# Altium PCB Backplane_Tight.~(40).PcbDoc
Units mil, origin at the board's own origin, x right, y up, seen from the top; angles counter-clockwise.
Board outline 6940 x 1650 mil, 6 copper layers (Top Layer, AGND, +5V, DGND, VCC, Bottom Layer), stack 50.76 mil thick; 21 components, 91 nets, 243 pads, 0 vias.
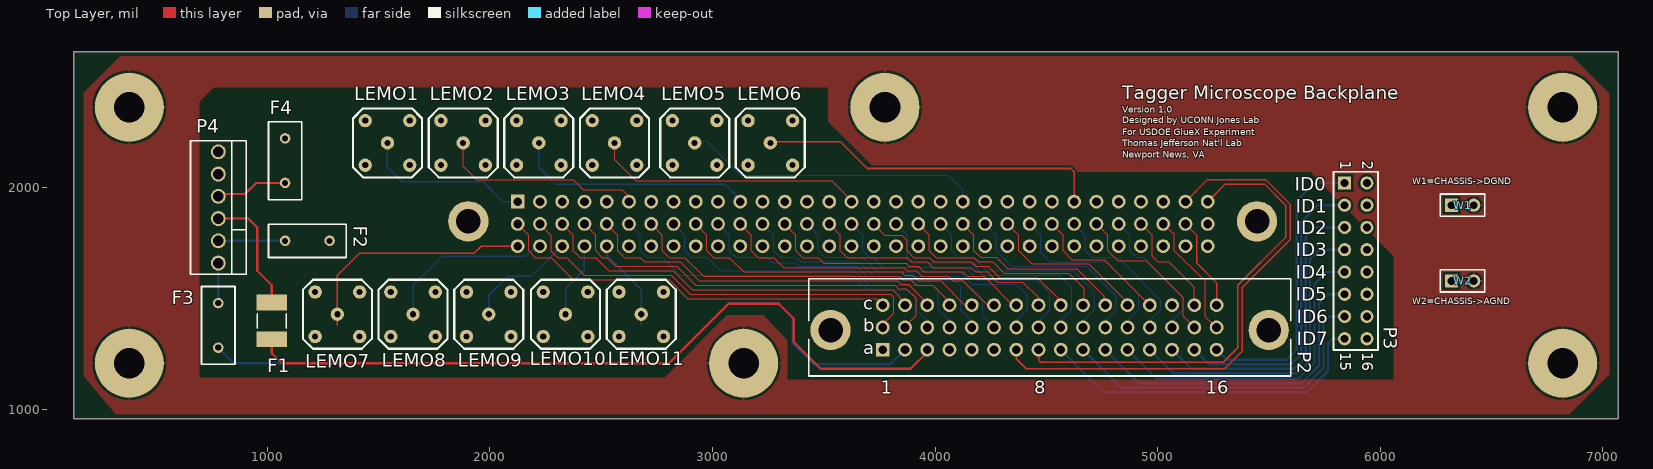
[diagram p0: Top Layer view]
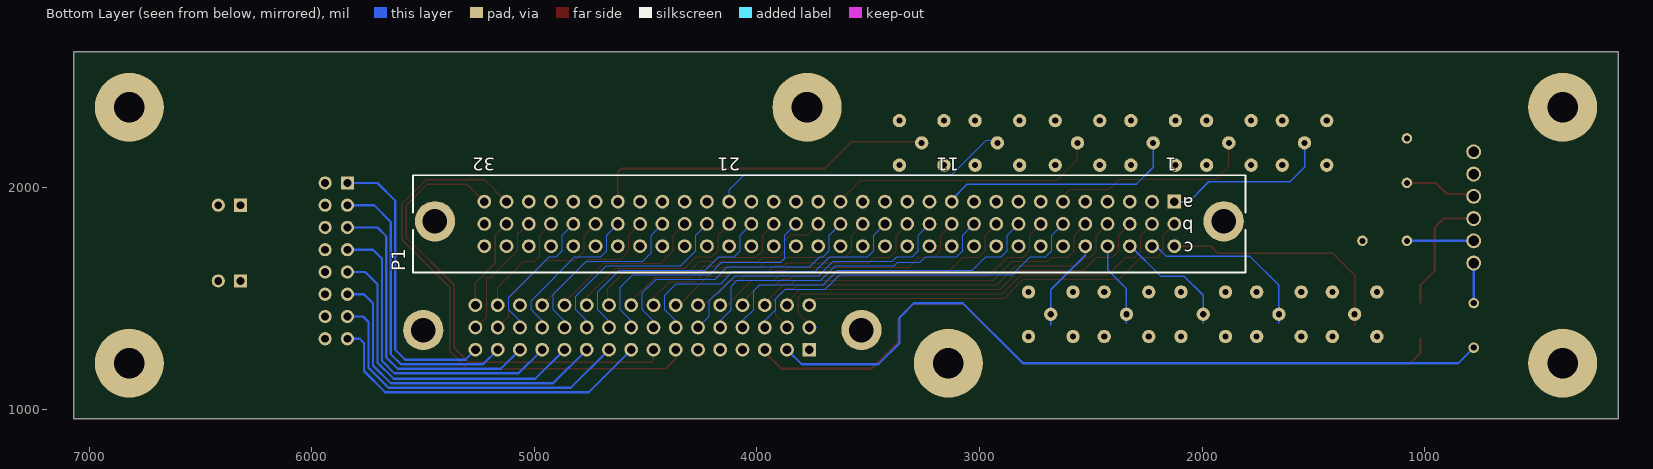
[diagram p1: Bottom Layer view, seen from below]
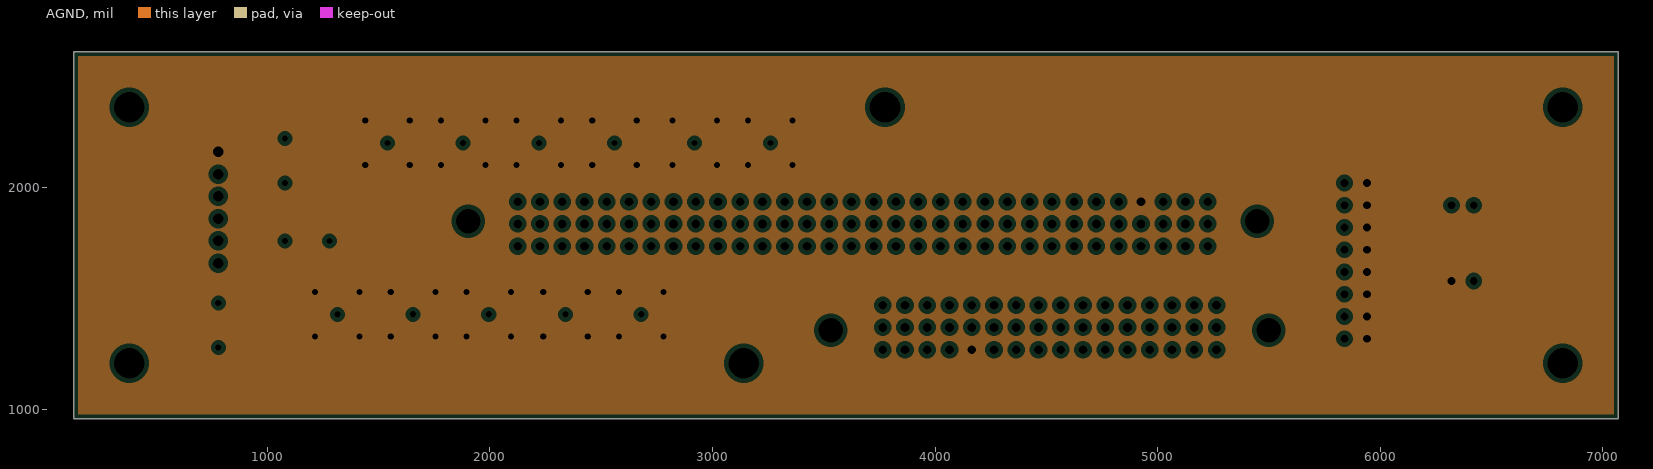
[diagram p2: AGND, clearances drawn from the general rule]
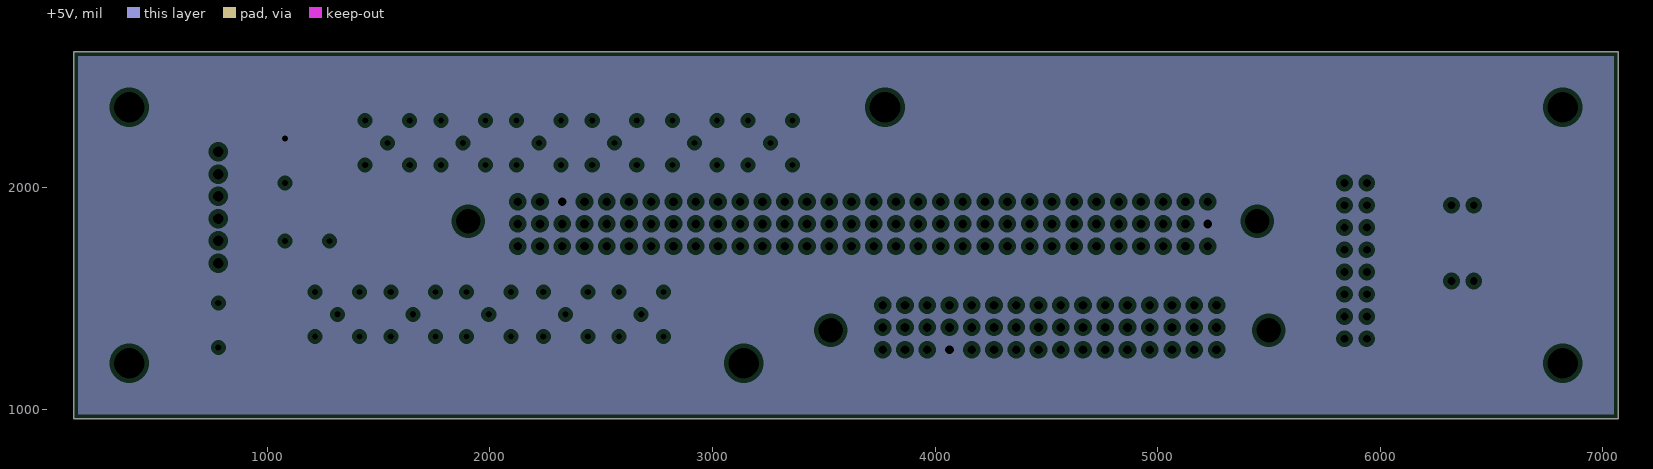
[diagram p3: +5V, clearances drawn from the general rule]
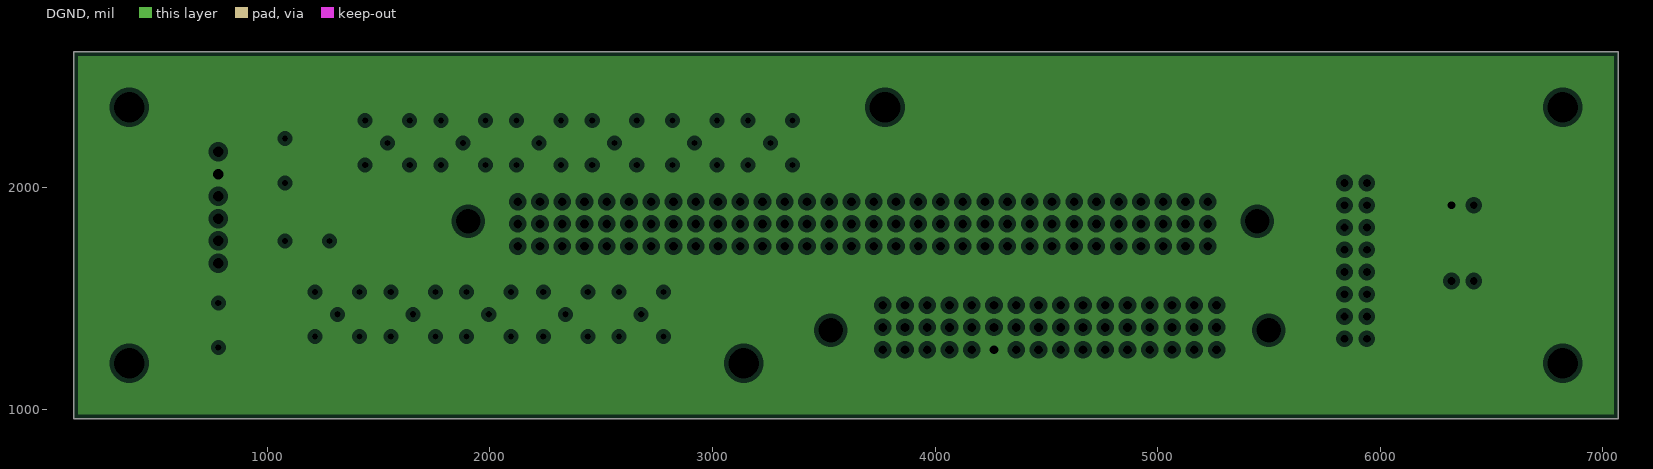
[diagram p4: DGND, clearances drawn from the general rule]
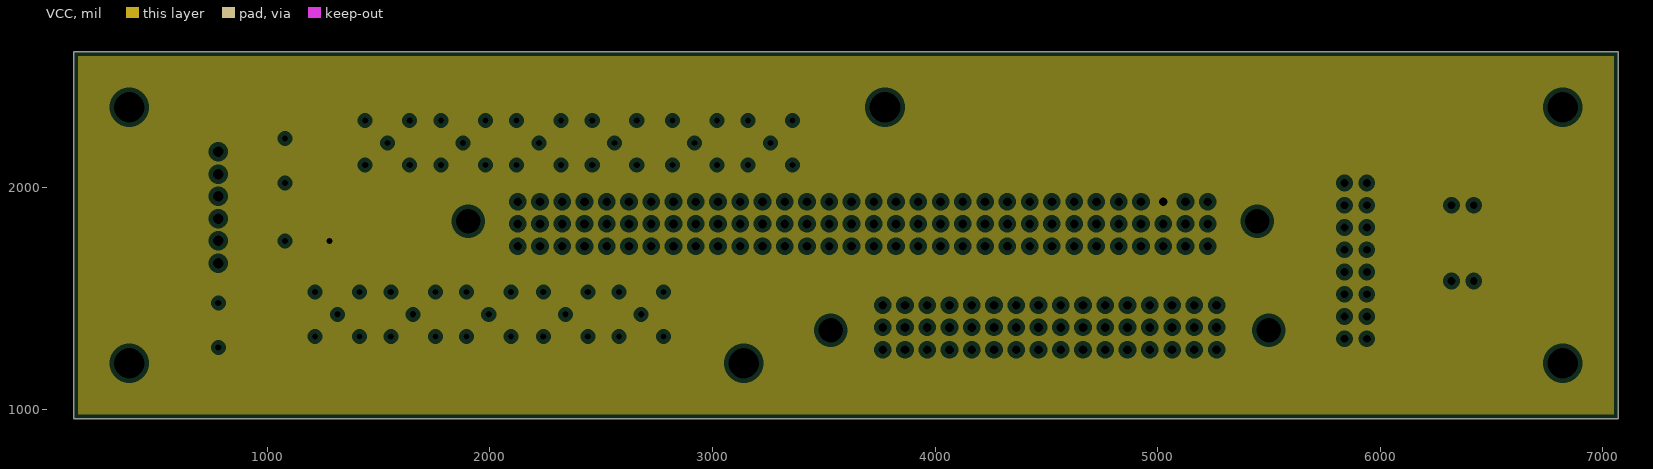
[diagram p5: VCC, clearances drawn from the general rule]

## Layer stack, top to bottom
Top Layer: signal copper 1.4
Dielectric: prepreg 5.1, FR-4, Dk 4.8
AGND: plane copper 1.4, net AGND
Dielectric: core 10.72, FR-4, Dk 4.8
+5V: plane copper 1.4, net +5V
Dielectric: prepreg 10.72, FR-4, Dk 4.8
DGND: plane copper 1.4, net DGND
Dielectric: core 10.72, FR-4, Dk 4.8
VCC: plane copper 1.4, net VCC
Dielectric: prepreg 5.1, FR-4, Dk 4.8
Bottom Layer: signal copper 1.4

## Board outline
130,960 7070,960 7070,2610 130,2610

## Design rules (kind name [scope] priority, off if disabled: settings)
Clearance Clearance_BIAS [InNetClass('BIAS')] p1: gap=15
Clearance [All] p2: gap=10
ComponentClearance [All] p1: gap=10 collisioncheckmode=3 verticalgap=10
PlaneClearance [All] p1: clearance=20
PlaneConnect [All] p1: planeconnectstyle=Relief reliefexpansion=20 reliefentries=4 reliefconductorwidth=10 reliefairgap=10
PolygonConnect [All] p1: connectstyle=Relief reliefconductorwidth=10 reliefentries=4 polygonreliefangle="90 Angle"
RoomDefinition LEMO [InComponentClass('LEMO')] p1: confinementstyle=ConfineIn formatcopy=TRUE lockcomponents=FALSE outline 275,1060 6580,1060 6580,2460 275,2460
RoomDefinition "Digital Connector" [InComponentClass('Digital Connector')] p2: confinementstyle=ConfineIn formatcopy=TRUE lockcomponents=FALSE outline 3170,1046 6595,1046 6595,2200 3170,2200
RoomDefinition "Analog Connector" [InComponentClass('Analog Connector')] p3: confinementstyle=ConfineIn formatcopy=TRUE lockcomponents=FALSE outline 1595,1516 5615,1516 5615,2191 1595,2191
RoutingVias [All] p1: holewidth=28 width=50 viastyle="Through Hole" minholewidth=28 minwidth=50 maxholewidth=28 maxwidth=50
SolderMaskExpansion [All] p1: expansion=4
SupplyNets VCC [OnLayer('VCC')] p1: voltage=10.00
SupplyNets +5V [OnLayer('+5V')] p2: voltage=5.000
SupplyNets DGND [OnLayer(DGND)] p3: voltage=0.000
SupplyNets AGND [OnLayer('AGND')] p4: voltage=0.000
TestPointUsage [All] p1: valid=0 allowmultiple=FALSE
Testpoint [All] p1: side=15 testpointundercomponent=TRUE minsize=40 maxsize=100 preferedsize=60 minholesize=0 maxholesize=40 preferedholesize=32 testpointgrid=1 style=1023 order=0123456789
Width Width_CHASSISGND [InNet('CHASSISGND')] p1: maxlimit=100 minlimit=10 preferedwidth=10
Width [All] p2: maxlimit=10 minlimit=5 preferedwidth=7
Width Width_BIAS [InNetClass('BIAS')] p3: maxlimit=10 minlimit=4 preferedwidth=5
Width Width_SIPMOUT [InNetClass('SIPMOUT')] p4: maxlimit=7.35 minlimit=2.1 preferedwidth=7.35 impedancedriven=TRUE minimp=50.000000 maximp=80.000000 favimp=50.000000
16 further rules are at their usual default settings.

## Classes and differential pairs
component class LEMO: F1 F2 F3 F4 LEMO1 LEMO2 LEMO3 LEMO4 LEMO5 LEMO6 LEMO7 LEMO8 LEMO9 LEMO10 LEMO11 P4 W1 W2
component class "Digital Connector": P2 P3 R?
component class "Analog Connector": P1
net class SIPMOUT: SIPMOUT1 SIPMOUT2 SIPMOUT3 SIPMOUT4 SIPMOUT5 SIPMOUT6 SIPMOUT7 SIPMOUT8 SIPMOUT9 SIPMOUT10 SIPMOUT11 SIPMOUT12 SIPMOUT13 SIPMOUT14 SIPMOUT15 SIPMOUT16 SIPMOUT17 SIPMOUT18 SIPMOUT19 SIPMOUT20 SIPMOUT21 SIPMOUT22 SIPMOUT23 SIPMOUT24 SIPMOUT25 SIPMOUT26 SIPMOUT27 SIPMOUT28 SIPMOUT29 SIPMOUT30 SIPMOUT31 SIPMOUT32 SUMMED1 SUMMED2 SUMMED3 SUMMED4 SUMMED5 SUMMED6
net class BIAS: SIPMBIAS1 SIPMBIAS2 SIPMBIAS3 SIPMBIAS4 SIPMBIAS5 SIPMBIAS6 SIPMBIAS7 SIPMBIAS8 SIPMBIAS9 SIPMBIAS10 SIPMBIAS11 SIPMBIAS12 SIPMBIAS13 SIPMBIAS14 SIPMBIAS15 SIPMBIAS16 SIPMBIAS17 SIPMBIAS18 SIPMBIAS19 SIPMBIAS20 SIPMBIAS21 SIPMBIAS22 SIPMBIAS23 SIPMBIAS24 SIPMBIAS25 SIPMBIAS26 SIPMBIAS27 SIPMBIAS28 SIPMBIAS29 SIPMBIAS30 SIPMBIAS31 SIPMBIAS32

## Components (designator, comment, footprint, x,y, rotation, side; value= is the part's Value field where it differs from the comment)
F1 "Fuse Thermal" CAPC4532M 1020,1400 r270 top
F2 "Fuse Thermal" RAD-0.2 1180,1760 r0 top
F3 "Fuse Thermal" RAD-0.2 780,1380 r270 top
F4 "Fuse Thermal" RAD-0.2 1080,2120 r90 top
LEMO1 "LEMO EPA.00" "LEMO EPA.00" 1540,2200 r0 top
LEMO2 "LEMO EPA.00" "LEMO EPA.00" 1880,2200 r0 top
LEMO3 "LEMO EPA.00" "LEMO EPA.00" 2220,2200 r0 top
LEMO4 "LEMO EPA.00" "LEMO EPA.00" 2560,2200 r0 top
LEMO5 "LEMO EPA.00" "LEMO EPA.00" 2920,2200 r0 top
LEMO6 "LEMO EPA.00" "LEMO EPA.00" 3260,2200 r0 top
LEMO7 "LEMO EPA.00" "LEMO EPA.00" 1315,1430 r0 top
LEMO8 "LEMO EPA.00" "LEMO EPA.00" 1655,1430 r0 top
LEMO9 "LEMO EPA.00" "LEMO EPA.00" 1995,1430 r0 top
LEMO10 "LEMO EPA.00" "LEMO EPA.00" 2340,1430 r0 top
LEMO11 "LEMO EPA.00" "LEMO EPA.00" 2680,1430 r0 top
P1 "DIN41612 96 pin, Backplane" EURO2.54-2V96 3675,1836 r0 bottom
P2 "DIN41612 48 pin, Backplane" EURO2.54-2V48 4515,1371 r0 top
P3 "Header 8X2" HDR2X8 5840,2020 r270 top
P4 "Header 6" KK6373 780,2160 r270 top
W1 "Jumper" HDR1X2 6320,1920 r0 top
W2 "Jumper" HDR1X2 6320,1580 r0 top

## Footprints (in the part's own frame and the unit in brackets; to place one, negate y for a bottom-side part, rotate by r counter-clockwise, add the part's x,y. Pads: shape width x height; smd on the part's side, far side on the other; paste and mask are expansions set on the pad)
CAPC4532M [mm] "Chip Capacitor, Body 4.5x3.2mm, IPC Low Density"
  rect 1.8x3.5 smd: 1(-2.1,0) 2(2.1,0)
  silkscreen extent -0.8,-1.65 0.8,1.65, body extent -2.4,-1.7 2.4,1.7, height 1.35
EURO2.54-2V48 [mil] "Connector; DIN 41612, Type 2C, Thru-Hole; Rows a+b+c, 48 Position; Vertical"
  round 181.1 hole 110.24: 17(-984.25,-11.81) 18(984.25,-11.81)
  rect 62x62 hole 39.37: A1(-750,-100)
  round 62 hole 39.37: A2(-650,-100) A3(-550,-100) A4(-450,-100) A5(-350,-100) A6(-250,-100) A7(-150,-100) A8(-50,-100) A9(50,-100) A10(150,-100) A11(250,-100) A12(350,-100) A13(450,-100) A14(550,-100) A15(650,-100) A16(750,-100) B1(-750,0) B2(-650,0) B3(-550,0) B4(-450,0) B5(-350,0) B6(-250,0) B7(-150,0) B8(-50,0) B9(50,0) B10(150,0) B11(250,0) B12(350,0) B13(450,0) B14(550,0) B15(650,0) B16(750,0) C1(-750,100) C2(-650,100) C3(-550,100) C4(-450,100) C5(-350,100) C6(-250,100) C7(-150,100) C8(-50,100) C9(50,100) C10(150,100) C11(250,100) C12(350,100) C13(450,100) C14(550,100) C15(650,100) C16(750,100)
  silkscreen extent -1083,-219 1083,219
EURO2.54-2V96 [mil] "Connector; DIN 41612, Type C, Thru-Hole; Rows a+b+c, 96 Position; Vertical"
  round 181.1 hole 110.24: 33(-1771.65,-11.81) 34(1771.65,-11.81)
  rect 62x62 hole 39.37: A1(-1550,-100)
  round 62 hole 39.37: A2(-1450,-100) A3(-1350,-100) A4(-1250,-100) A5(-1150,-100) A6(-1050,-100) A7(-950,-100) A8(-850,-100) A9(-750,-100) A10(-650,-100) A11(-550,-100) A12(-450,-100) A13(-350,-100) A14(-250,-100) A15(-150,-100) A16(-50,-100) A17(50,-100) A18(150,-100) A19(250,-100) A20(350,-100) A21(450,-100) A22(550,-100) A23(650,-100) A24(750,-100) A25(850,-100) A26(950,-100) A27(1050,-100) A28(1150,-100) A29(1250,-100) A30(1350,-100) A31(1450,-100) A32(1550,-100) B1(-1550,0) B2(-1450,0) B3(-1350,0) B4(-1250,0) B5(-1150,0) B6(-1050,0) B7(-950,0) B8(-850,0) B9(-750,0) B10(-650,0) B11(-550,0) B12(-450,0) B13(-350,0) B14(-250,0) B15(-150,0) B16(-50,0) B17(50,0) B18(150,0) B19(250,0) B20(350,0) B21(450,0) B22(550,0) B23(650,0) B24(750,0) B25(850,0) B26(950,0) B27(1050,0) B28(1150,0) B29(1250,0) B30(1350,0) B31(1450,0) B32(1550,0) C1(-1550,100) C2(-1450,100) C3(-1350,100) C4(-1250,100) C5(-1150,100) C6(-1050,100) C7(-950,100) C8(-850,100) C9(-750,100) C10(-650,100) C11(-550,100) C12(-450,100) C13(-350,100) C14(-250,100) C15(-150,100) C16(-50,100) C17(50,100) C18(150,100) C19(250,100) C20(350,100) C21(450,100) C22(550,100) C23(650,100) C24(750,100) C25(850,100) C26(950,100) C27(1050,100) C28(1150,100) C29(1250,100) C30(1350,100) C31(1450,100) C32(1550,100)
  silkscreen extent -1870,-219 1870,219
HDR1X2 [mm] "Connector; Header; 2 Position"
  rect 1.5x1.5 hole 0.9: 1(0,0)
  round 1.5 hole 0.9: 2(2.54,0)
  silkscreen extent -1.27,-1.27 3.81,1.27
HDR2X8 [mm] "Connector; Header; 8x2 Position"
  rect 1.5x1.5 hole 0.9: 1(0,0)
  round 1.5 hole 0.9: 2(0,2.54) 3(2.54,0) 4(2.54,2.54) 5(5.08,0) 6(5.08,2.54) 7(7.62,0) 8(7.62,2.54) 9(10.16,0) 10(10.16,2.54) 11(12.7,0) 12(12.7,2.54) 13(15.24,0) 14(15.24,2.54) 15(17.78,0) 16(17.78,2.54)
  silkscreen extent -1.27,-1.27 19.05,3.81
KK6373 [mil]
  round 67 hole 47.24: 1(0,0) 2(100,0) 3(200,0) 4(300,0) 5(400,0) 6(500,0)
  silkscreen extent -50,-125 550,125
"LEMO EPA.00" [mil]
  round 60 hole 27.56: 0(0,0) 1(-100,100) 2(100,100) 3(100,-100) 4(-100,-100)
  silkscreen extent -155,-155 155,155
RAD-0.2 [mm] "Jumper Wire; 2 Leads"
  round 1.2 hole 0.7: 1(-2.54,0) 2(2.54,0)
  silkscreen extent -4.44,-1.91 4.44,1.91

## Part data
F1 F2 F3 F4: "Thermal Fuse"
P3: library part "Header 5X2", "Header, 5-Pin, Dual row"
P4: "Header, 6-Pin"
W1 W2: "Jumper Wire"

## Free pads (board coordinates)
  round 310 hole 138 unplated: 0(380,1210) 0(380,2360) 0(3140,1210) 0(3775,2360) 0(6820,1210) 0(6820,2360)

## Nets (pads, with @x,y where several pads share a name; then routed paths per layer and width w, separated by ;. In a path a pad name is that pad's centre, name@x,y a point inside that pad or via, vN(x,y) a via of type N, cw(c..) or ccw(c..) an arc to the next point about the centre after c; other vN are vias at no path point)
+5V: F4.2 P1.A3 P1.B32 P2.A4
+5V_FUSE: F4.1 P4.3 | length 325.7
  Top Layer w10: P4.3@775,1970 900,1970 950,2020 F4.1
+210V: F3.2 P2.A2 | length 3434.4
  Bottom Layer w10: F3.2 850,1210 2805,1210 3075,1480 3295,1480 3360,1415 3360,1300 3455,1205 3799,1205 P2.A2
+210V_FUSE: F3.1 P4.6 | length 180
  Bottom Layer w10: F3.1 P4.6
-5V: F1.2 P2.A3 | length 3361.5
  Top Layer w10: F1.2 1020,1255 1065,1210 2805,1210 3072.5,1477.5 3297.5,1477.5 3365,1410 3365,1305 3485,1185 3890,1185 3965,1260 P2.A3
-5V_FUSE: F1.1 P4.4 | length 565.8
  Top Layer w10: P4.4@770,1860 915,1860 955,1820 955,1625 1020,1560 F1.1
ADC_EXT1: P1.A31 P2.A7 | length 2413.4
  Top Layer w7: P2.A7 4365,1230 4410,1185 5300,1185 5380,1265 5380,1550 5595,1765 5595,1925 5485,2035 5224,2035 P1.A31
ADC_EXT2: P1.A32 P2.A8 | length 2123.2
  Top Layer w7: P2.A8 4465,1225 4475,1215 5295,1215 5360,1280 5360,1560 5575,1775 5575,1920 5480,2015 5304,2015 P1.A32
AGND: LEMO1.1 LEMO1.2 LEMO1.3 LEMO1.4 LEMO2.1 LEMO2.2 LEMO2.3 LEMO2.4 LEMO3.1 LEMO3.2 LEMO3.3 LEMO3.4 LEMO4.1 LEMO4.2 LEMO4.3 LEMO4.4 LEMO5.1 LEMO5.2 LEMO5.3 LEMO5.4 LEMO6.1 LEMO6.2 LEMO6.3 LEMO6.4 LEMO7.1 LEMO7.2 LEMO7.3 LEMO7.4 LEMO8.1 LEMO8.2 LEMO8.3 LEMO8.4 LEMO9.1 LEMO9.2 LEMO9.3 LEMO9.4 LEMO10.1 LEMO10.2 LEMO10.3 LEMO10.4 LEMO11.1 LEMO11.2 LEMO11.3 LEMO11.4 P1.A29 P2.A5 P3.2 P3.4 P3.6 P3.8 P3.10 P3.12 P3.14 P3.16 P4.1 W2.1
CHASSISGND: pad.0 W1.2 W2.2
CP2201/LA: P2.A1
DGND: P2.A6 P4.2 W1.1
ID0: P2.A16 P3.1 | length 1314.4
  Bottom Layer w10: P2.A16 5310,1226 5580,1226 5625,1271 5625,1940 5705,2020 P3.1
ID1: P2.A15 P3.3 | length 1346.5
  Bottom Layer w10: P2.A15 5231,1205 5599,1205 5645,1251 5645,1845 5720,1920 P3.3
ID2: P2.A14 P3.5 | length 1392.3
  Bottom Layer w10: P2.A14 5151,1185 5614,1185 5665,1236 5665,1780 5705,1820 P3.5
ID3: P2.A13 P3.7 | length 1417.7
  Bottom Layer w10: P2.A13 5071,1165 5629,1165 5685,1221 5685,1680 5725,1720 P3.7
ID4: P2.A12 P3.9 | length 1434.4
  Bottom Layer w10: P2.A12 4996,1140 5632.28,1140 5705,1212.72 5705,1565 5760,1620 P3.9
ID5: P2.A11 P3.11 | length 1467.3
  Bottom Layer w10: P2.A11 4916,1120 5645,1120 5725,1200 5725,1480 5765,1520 P3.11
ID6: P2.A10 P3.13 | length 1498.5
  Bottom Layer w10: P2.A10 4836,1100 5655,1100 5745,1190 5745,1395 5770,1420 P3.13
ID7: P2.A9 P3.15 | length 1526.7
  Bottom Layer w10: P2.A9 4756,1080 5670,1080 5765,1175 5765,1300 5785,1320 P3.15
SIPMBIAS1: P1.B1 P2.C1 | length 1832.8
  Top Layer w5: P1.B1 2175,1786 2175,1715 2205,1685 2275,1685 2375,1585 2805,1585 2890,1500 3736,1500 P2.C1
SIPMBIAS2: P1.B2 P2.B1 | length 1974.4
  Top Layer w5: P1.B2 2225,1835 2276.5,1783.5 2276.5,1713.5 2305,1685 2345,1685 2425,1605 2815,1605 2900,1520 3800,1520 3815,1505 3815,1435 3765,1385 P2.B1
  Bottom Layer w5: P1.B2@2225,1825 P1.B2 ; P2.B1@3765,1376 P2.B1 P2.B1@3770,1371
  Bottom Layer w10: P2.B1@3735,1371 P2.B1
SIPMBIAS3: P1.B3 P2.C2 | length 1741
  Top Layer w5: P1.B3 2375,1786 2375,1715 2405,1685 2475,1685 2535,1625 2825,1625 2910,1540 3810,1540 3865,1485 P2.C2
SIPMBIAS4: P1.B4 P2.B2 | length 1851.5
  Top Layer w5: P1.B4 2475,1786 2475,1715 2505,1685 2525,1685 2565,1645 2840,1645 2925,1560 3820,1560 3835,1545 3871.72,1545 3915,1501.72 3915,1425 3865,1375 P2.B2
  Bottom Layer w5: P2.B2 P2.B2@3865,1401
SIPMBIAS5: P1.B5 P2.C3 | length 1663.1
  Top Layer w5: P1.B5 2575,1786 2575,1715 2605,1685 2675,1685 2695,1665 2855,1665 2940,1580 3830,1580 3845,1565 3880,1565 3965,1480 P2.C3
  Bottom Layer w5: P2.C3 P2.C3@3965,1496
SIPMBIAS6: P1.B6 P2.B3 | length 1634.6
  Bottom Layer w5: P1.B6 2675,1786 2675,1716 2705,1686 2775,1686 2855,1606 3630,1606 3695,1541 3875,1541 3920,1496 3920,1491 3915,1486 3915,1451 3965,1401 P2.B3 P2.B3@3975,1371
SIPMBIAS7: P1.B7 P2.C4 | length 1546.1
  Top Layer w5: P1.B7 2775,1786 2775,1715 2805,1685 2875,1685 2960,1600 3840,1600 3855,1585 3890,1585 3915,1560 3990,1560 4075,1475 P2.C4@4080,1475
SIPMBIAS8: P1.B8 P2.B4 | length 1541
  Bottom Layer w5: P1.B8 2875,1786 2875,1716 2905,1686 2975,1686 3035,1626 3640,1626 3705,1561 3990,1561 4015,1536 4015,1451 4065,1401 P2.B4
SIPMBIAS9: P1.B9 P2.C5 | length 1432.8
  Top Layer w5: P1.B9 2975,1786 2975,1715 3005,1685 3075,1685 3140,1620 3850,1620 3865,1605 3900,1605 3925,1580 4025,1580 4134,1471 P2.C5
SIPMBIAS10: P1.B10 P2.B5 | length 1452.7
  Bottom Layer w5: P1.B10 3075,1786 3075,1716 3105,1686 3245,1686 3270,1661 3370,1661 3385,1646 3651.41,1646 3716.41,1581 4090,1581 4115,1556 4115,1451 4165,1401 P2.B5
SIPMBIAS11: P1.B11 P2.C6 | length 1332.8
  Top Layer w5: P1.B11 3175,1786 3175,1715 3205,1685 3275,1685 3320,1640 3860,1640 3875,1625 3915,1625 3940,1600 4060,1600 4080,1580 4127,1580 4236,1471 P2.C6
SIPMBIAS12: P1.B12 P2.B6 | length 1334.6
  Bottom Layer w5: P1.B12 3275,1786 3275,1716 3305,1686 3375,1686 3395,1666 3660,1666 3725,1601 4100,1601 4180,1521 4185,1521 4215,1491 4215,1421 P2.B6 P2.B6@4265,1391
SIPMBIAS13: P1.B13 P2.C7 | length 1232.8
  Top Layer w5: P1.B13 3375,1786 3375,1715 3405,1685 3475,1685 3500,1660 3870,1660 3885,1645 3925,1645 3950,1620 4125,1620 4145,1600 4220,1600 4349,1471 P2.C7
SIPMBIAS14: P1.B14 P2.B7 | length 1334.3
  Bottom Layer w5: P1.B14 3475,1786 3475,1716 3505,1686 3675,1686 3740,1621 4110,1621 4165,1566 4365,1566 4415,1516 4415,1451 4365,1401 P2.B7 P2.B7@4370,1371
SIPMBIAS15: P1.B15 P2.C8 | length 1152.7
  Top Layer w5: P1.B15 3575,1786 3575,1715 3605,1685 3875,1685 3895,1665 3965,1665 3990,1640 4160,1640 4180,1620 4235,1620 4280,1575 4395,1575 4465,1505 P2.C8
SIPMBIAS16: P1.B16 P2.B8 | length 1240.1
  Bottom Layer w5: P1.B16 3675,1786 3675,1716 3705,1686 3720,1686 3765,1641 4135,1641 4190,1586 4455,1586 4515,1526 4515,1451 4465,1401 P2.B8 P2.B8@4470,1371
SIPMBIAS17: P1.B17 P2.C9 | length 1029.3
  Top Layer w5: P1.B17 3725,1835 3775,1785 3850,1785 3875,1760 3875,1715 3905,1685 3975,1685 3995,1665 4165,1665 4185,1645 4240,1645 4290,1595 4460,1595 4565,1490 P2.C9
SIPMBIAS18: P1.B18 P2.B9 | length 1170.3
  Bottom Layer w5: P1.B18 3875,1786 3875,1681 3895,1661 4160,1661 4215,1606 4560,1606 4615,1551 4615,1451 4565,1401 P2.B9
SIPMBIAS19: P1.B19 P2.C10 | length 996.5
  Top Layer w5: P1.B19 3975,1786 3975,1715 4005,1685 4175,1685 4195,1665 4260,1665 4310,1615 4600,1615 4670,1545 4670,1471 4669,1470 P2.C10@4655,1470
SIPMBIAS20: P1.B20 P2.B10 | length 1048.1
  Bottom Layer w5: P1.B20 4075,1786 4075,1716 4105,1686 4175,1686 4235,1626 4620,1626 4715,1531 4715,1451 4665,1401 P2.B10 P2.B10@4675,1371
SIPMBIAS21: P1.B21 P2.C11 | length 870.6
  Top Layer w5: P1.B21 4175,1786 4175,1716 4205,1686 4275,1686 4326,1635 4636,1635 4760,1511 P2.C11@4760,1461 ; P2.C11 P2.C11@4765,1481
SIPMBIAS22: P1.B22 P2.B11 | length 926.3
  Bottom Layer w5: P1.B22 4275,1786 4275,1716 4345,1646 4680,1646 4815,1511 4815,1451 4765,1401 P2.B11
SIPMBIAS23: P1.B23 P2.C12 | length 738.1
  Top Layer w5: P1.B23 4375,1786 4375,1716 4435,1656 4690,1656 4865,1481 P2.C12
SIPMBIAS24: P1.B24 P2.B12 | length 838.1
  Bottom Layer w5: P1.B24 4475,1786 4475,1706 4515,1666 4770,1666 4915,1521 4915,1451 4865,1401 P2.B12
SIPMBIAS25: P1.B25 P2.C13 | length 639.3
  Top Layer w5: P1.B25@4520,1841 4575,1786 4575,1716 4615,1676 4760,1676 P2.C13
SIPMBIAS26: P1.B26 P2.B13 | length 724.6
  Bottom Layer w5: P1.B26 4675,1786 4675,1716 4705,1686 4820,1686 5015,1491 5015,1451 4965,1401 P2.B13 P2.B13@4975,1371
SIPMBIAS27: P1.B27 P2.B15 | length 722.8
  Top Layer w5: P1.B27 4775,1786 4775,1716 4820,1671 4949,1671 5115,1505 5115,1421 P2.B15
SIPMBIAS28: P1.B28 P2.B14 | length 628.4
  Bottom Layer w5: P1.B28 4875,1786 4875,1716 4905,1686 4935,1686 5115,1506 5115,1451 5065,1401 P2.B14 P2.B14@5070,1371
SIPMBIAS29: P1.B29 P2.C15 | length 518.7
  Top Layer w5: P1.B29 4975,1786 4975,1691 5000,1666 5050,1666 5165,1551 P2.C15
  Bottom Layer w5: P2.C15 P2.C15@5165,1496
SIPMBIAS30: P1.B30 P2.B16 | length 578.6
  Top Layer w5: P1.B30 5065,1796 5075,1796 5075,1716 5200,1591 5215,1591 5215,1420 P2.B16@5264,1371
SIPMBIAS31: P1.B31 P2.C16 | length 423
  Top Layer w7: P1.B31 5175,1786 5175,1661 5265,1571 P2.C16
SIPMOUT1: LEMO7.0 P1.C1 | length 1089.3
  Top Layer w7: 1315,1380 1315,1605 1415,1705 1930,1705 1961,1736 P1.C1
SIPMOUT2: LEMO8.0 P1.C2 | length 812.9
  Bottom Layer w7: 1655,1390 1655,1560 1785,1690 2160,1690 2206,1736 P1.C2
SIPMOUT3: LEMO9.0 P1.C3 | length 546.5
  Bottom Layer w7: 1995,1390 1995,1515 2080,1600 2185,1600 2321,1736 P1.C3
SIPMOUT4: LEMO10.0 P1.C4 | length 381.2
  Bottom Layer w7: 2340,1390 2340,1545 2425,1630 P1.C4
SIPMOUT5: LEMO11.0 P1.C5 | length 420.2
  Bottom Layer w7: P1.C5 2525,1695 2680,1540 2680,1380
SIPMOUT6: P1.C6
SIPMOUT7: P1.C7
SIPMOUT8: P1.C8
SIPMOUT9: P1.C9
SIPMOUT10: P1.C10
SIPMOUT11: P1.C11
SIPMOUT12: P1.C12
SIPMOUT13: P1.C13
SIPMOUT14: P1.C14
SIPMOUT15: P1.C15
SIPMOUT16: P1.C16
SIPMOUT17: P1.C17
SIPMOUT18: P1.C18
SIPMOUT19: P1.C19
SIPMOUT20: P1.C20
SIPMOUT21: P1.C21
SIPMOUT22: P1.C22
SIPMOUT23: P1.C23
SIPMOUT24: P1.C24
SIPMOUT25: P1.C25
SIPMOUT26: P1.C26
SIPMOUT27: P1.C27
SIPMOUT28: P1.C28
SIPMOUT29: P1.C29
SIPMOUT30: P1.C30
SIPMOUT31: P1.C31
SIPMOUT32: P1.C32
SUMMED1: LEMO1.0 P1.A1 | length 768.8
  Bottom Layer w7: LEMO1.0@1540,2210 1540,2090 1605,2025 1970,2025 2059,1936 P1.A1
SUMMED2: LEMO2.0 P1.A6 | length 939.9
  Top Layer w5: LEMO2.0@1880,2210 1880,2095 1940,2035 2375,2035 2420,1990 2595,1990 2625,1960 P1.A6
SUMMED3: LEMO3.0 P1.A11 | length 1094.1
  Bottom Layer w7: LEMO3.0@2220,2210 2220,2090 2295,2015 3055,2015 3125,1945 P1.A11
SUMMED4: LEMO4.0 P1.A16 | length 1230.6
  Top Layer w5: LEMO4.0@2560,2210 2560,2125 2655,2030 3535,2030 3625,1940 P1.A16
SUMMED5: LEMO5.0 P1.A21 | length 1354.3
  Bottom Layer w5: LEMO5.0@2920,2220 2930,2210 2972.5,2210 3127.5,2055 4060,2055 4125,1990 P1.A21
SUMMED6: LEMO6.0 P1.A26 | length 1539.9
  Top Layer w7: LEMO6.0@3275,2205 3575,2205 3695,2085 4610,2085 4625,2070 P1.A26
VCC: F2.2 P1.A30
VCC_FUSE: F2.1 P4.5 | length 300
  Bottom Layer w10: P4.5 F2.1
pads on no net: P1.33 P1.34 P1.A2 P1.A4 P1.A5 P1.A7 P1.A8 P1.A9 P1.A10 P1.A12 P1.A13 P1.A14 P1.A15 P1.A17 P1.A18 P1.A19 P1.A20 P1.A22 P1.A23 P1.A24 P1.A25 P1.A27 P1.A28 P2.17 P2.18 P2.C14

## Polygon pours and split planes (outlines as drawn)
CHASSISGND on Top Layer "+5V" (solid, pour order 1002): 3520,2450 3720,2590 6860,2590 7030,2420 7030,1160 6850,980 6060,980 6060,1690.83 5685,2070 3745,2070 3520,2295
CHASSISGND on Top Layer "+5V" (solid, pour order 1000): 3095.42,980 6255,980 6255,1135.16 3315,1135
CHASSISGND on Top Layer "+5V" (solid, pour order 1000): 629.81,1145 2785,1145 3065,1425 3228.57,1425 3335,1313.25 3335,1135 3128.33,980 477.04,980
CHASSISGND on Top Layer "+5V" (solid, pour order 1001): 3753.33,2590 340,2590 175,2425 175,1154 320,980 532.5,980 695,1110 695,2385 760,2450 3560,2450
DGND on DGND (split plane): 7049.61,980.39 150.39,980.39 150.39,2589.61 7049.61,2589.61
AGND on AGND (split plane): 7049.61,980.39 150.39,980.39 150.39,2589.61 7049.61,2589.61
+5V on +5V (split plane): 7049.61,980.39 150.39,980.39 150.39,2589.61 7049.61,2589.61
VCC on VCC (split plane): 7049.61,980.39 150.39,980.39 150.39,2589.61 7049.61,2589.61

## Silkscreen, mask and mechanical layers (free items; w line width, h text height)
Top Overlay:
  text "Tagger Microscope Backplane" at 4840,2395 h60
  text "Version 1.0" at 4840,2336 h30
  text "Designed by UCONN Jones Lab" at 4840,2289 h30
  text "For USDOE GlueX Experiment" at 4842,2234 h30
  text "Thomas Jefferson Nat'l Lab" at 4842,2184 h30
  text "Newport News, VA" at 4842,2133 h30
  text "W1=CHASSIS->DGND" at 6145,2015 h30
  text "ID0" at 5615,1985 h60
  text "ID1" at 5620,1885 h60
  text "ID2" at 5620,1790 h60
  text "ID3" at 5620,1690 h60
  text "ID4" at 5620,1590 h60
  text "ID5" at 5620,1490 h60
  text "W2=CHASSIS->AGND" at 6145,1475 h30
  text "ID6" at 5625,1390 h60
  text "ID7" at 5625,1290 h60

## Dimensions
380,1210 to 380,2360 on Top Overlay
380,1210 to 3140,1210 on Top Overlay
380,2360 to 3775,2360 on Top Overlay
3775,2360 to 6820,2360 on Top Overlay
6820,2360 to 6820,1210 on Top Overlay
3140,1210 to 6820,1210 on Top Overlay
